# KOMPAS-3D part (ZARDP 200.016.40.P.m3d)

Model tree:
1. Поверхность без истории:1
2. Поверхность без истории:2
3. Поверхность без истории:3
4. Поверхность без истории:4
5. Поверхность без истории:5
6. Поверхность без истории:6
7. Поверхность без истории:7
8. Поверхность без истории:8
9. Поверхность без истории:9
10. Поверхность без истории:10
11. Поверхность без истории:11
12. Поверхность без истории:12
13. Поверхность без истории:13
14. Поверхность без истории:14
15. Поверхность без истории:15
16. Поверхность без истории:16
17. Поверхность без истории:17
18. Поверхность без истории:18
19. Поверхность без истории:19
20. Поверхность без истории:20
21. Поверхность без истории:21
22. Поверхность без истории:22
23. Поверхность без истории:23
24. Поверхность без истории:24
25. Поверхность без истории:25
26. Поверхность без истории:26
27. Поверхность без истории:27
28. Поверхность без истории:28
29. Поверхность без истории:29
30. Поверхность без истории:30
31. Поверхность без истории:31
32. Поверхность без истории:32
33. Поверхность без истории:33
34. Поверхность без истории:34
35. Поверхность без истории:35
36. Поверхность без истории:36
37. Поверхность без истории:37
38. Поверхность без истории:38
39. Поверхность без истории:39
40. Поверхность без истории:40
41. Поверхность без истории:41
42. Поверхность без истории:42
43. Поверхность без истории:43
44. Поверхность без истории:44
45. Поверхность без истории:45
46. Поверхность без истории:46
47. Поверхность без истории:47
48. Поверхность без истории:48
49. Поверхность без истории:49
50. Поверхность без истории:50
51. Поверхность без истории:51
52. Поверхность без истории:52
53. Поверхность без истории:53
54. Поверхность без истории:54
55. Поверхность без истории:55
56. Поверхность без истории:56
57. Поверхность без истории:57
58. Поверхность без истории:58
59. Поверхность без истории:59
60. Поверхность без истории:60
61. Поверхность без истории:61
62. Поверхность без истории:62
63. Поверхность без истории:63
64. Поверхность без истории:64
65. Поверхность без истории:65
66. Поверхность без истории:66
67. Поверхность без истории:67
68. Поверхность без истории:68
69. Поверхность без истории:69
70. Поверхность без истории:70
71. Поверхность без истории:71
72. Поверхность без истории:72
73. Поверхность без истории:73
74. Поверхность без истории:74
75. Поверхность без истории:75
76. Поверхность без истории:76
77. Поверхность без истории:77
78. Поверхность без истории:78
79. Поверхность без истории:79
80. Поверхность без истории:80
81. Поверхность без истории:81
82. Поверхность без истории:82
83. Поверхность без истории:83
84. Поверхность без истории:84
85. Поверхность без истории:85
86. Поверхность без истории:86
87. Поверхность без истории:87
88. Поверхность без истории:88
89. Поверхность без истории:89
90. Поверхность без истории:90
91. Поверхность без истории:91
92. Поверхность без истории:92
93. Поверхность без истории:93
94. Поверхность без истории:94
95. Поверхность без истории:95
96. Поверхность без истории:96
97. Поверхность без истории:97
98. Поверхность без истории:98
99. Поверхность без истории:99
100. Поверхность без истории:100
101. Поверхность без истории:101
102. Поверхность без истории:102
103. Поверхность без истории:103
104. Поверхность без истории:104
105. Поверхность без истории:105
106. Поверхность без истории:106
107. Поверхность без истории:107
108. Поверхность без истории:108
109. Поверхность без истории:109

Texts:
  ЗАРДП 200-016-40-Р(АВ550) КП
